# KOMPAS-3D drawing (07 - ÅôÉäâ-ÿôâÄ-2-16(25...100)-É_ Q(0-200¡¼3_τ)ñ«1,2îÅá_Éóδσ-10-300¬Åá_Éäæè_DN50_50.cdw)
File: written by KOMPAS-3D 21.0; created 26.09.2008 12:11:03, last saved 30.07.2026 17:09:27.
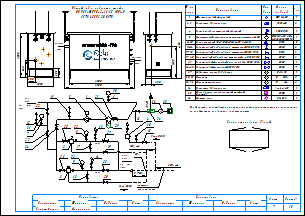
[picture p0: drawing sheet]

Sheets 1-2: A3, landscape

Document properties: Наименование: Макро:21; Автор: RaskoAdmin; Форматы листов документа: 2xA3; Полное имя файла: \\ur38nt01\Departments\КТО\КБ ПУРДГ\Заявки\Прайс-лист на типовые шкафы ГРПШ\ПУРДГ_стандарт_30_04_2026\ПУРДГ с РДСК\ПУРДГ-ШУГО-2-16(25...100)-Р_ Q(0-200нм3_ч)до1,2МПа_Рвых-10-300кПа_РДСК_DN50_50.cdw

Title block, sheet 1: Наименование: Пункт учета газа / ПУГ-Ш-400-Р / ЛГТИ.485922.001ТУ; designation: ЛГТИ.03.4411141; sheet number: 1; Количество листов документа: 2; organisation: ООО "ЭЛЬСТЕР Газэлектроника"; Форматы листов документа: A3; stored path: C:\Рабочие документы\Компас\ПУГ\Схема.cdw; Разработал: Устинов; Проверил: Кошкин; Утвердил: Кошкин
Title block, sheet 2: sheet number: 2; stored path: D:\Рабочие документы\Заявки\ПУРДГ\ПУРДГ-ШУЭО-2-100-Р 4411220.cdw; designation, second copy: ЛГТИ.03.4411141-

Views: Вид 1, Вид 2
Referenced files: wcvoit.frw
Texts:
  Normal
  № на
  схеме
  Усл.
  обозн.
  Марка
  (модель)
  Кол.
  Фильтр газовый фланцевый
  ФГ 16-50
  Регулятор давления газа
  РДСК-50
  Клапан предохранительный сбросной
  КПС DN20
  Измерительный комплекс с ротационным счетчиком Ду50
  СГ-ЭК-Р-(0,2...2,0)-
  Кран кнопочный VE-РАСКО-НЗ-1,6-G1/2-М20
  DN15
  Кран шаровой "под приварку" штуцерный DN20 PN16
  DN20
  Кран шаровой "под приварку" штуцерный DN15 PN16
  Кран шаровой "под приварку" штуцерный п/п DN20 PN16
  Кран шаровой фланцевый с мех. приводом DN50 PN16
  Кран шаровой фланцевый DN50 PN16
  DN50
  Индикатор перепада давления
  Манометр
  Манометр-напоромер
  Обогреватель газогорелочный шкафной
  (Эльтон")
  Счетчик газа
  Delta 15
  0...     МПа
  0...     кПа
  Venio-A-15
  ОГШН
  BK-G1,6
  Общий вид и габариты шкафа
  ПУРДГ-ШУГО-2-16(25...100)-Р
  Выход газа
  Вход газа
  logo-rasko-ge.png
  DN 1
  местное
  сопротивление
  Римп DN20
  Выход
  газа
  Р=     кПа
  Вход
  Р=       МПа
  PDI
  Схема открывания дверей
  Предприятие изготовитель может заменять комплектующие на аналогичные,
  не ухудшающие заявленных характеристик.
  Должность
  Конструктор
  Фамилия
  Подпись
  Дата
  Согласовано
  Максимкин
  Лист
  Листов
  POLYLINE_STYLE_0.18_RGB_0_0_0
  POLYLINE_STYLE_0.50_RGB_0_0_0
  POLYLINE_STYLE_0.34_RGB_0_0_0
  PHANTOM_RGB_0_0_0_SC_1_THICK_0.18
  K5LT_THIN_RGB_0_0_0_THICK_0.18
  K5LT32769_RGB_0_0_0_THICK_0.18
  K5LT12_RGB_0_0_0_SC_1_THICK_0.18
  K5LT_DASHED_RGB_0_0_0_SC_1_THICK_0.18
  ACISOTGL_RGB_0_0_0_SC_0.8_THICK_0.25
  CONTINUOUS_RGB_0_127_31_THICK_0.3
  CONTINUOUS_RGB_0_0_255_THICK_0.35
  CONTINUOUS_RGB_255_0_0_THICK_0.35
  POLYLINE_STYLE_0.25_RGB_0_0_0
  CONTINUOUS_RGB_0_0_0_THICK_0.5
  POLYLINE_STYLE_0.35_RGB_0_0_255
  CONTINUOUS_RGB_0_0_0_THICK_0.4
  CONTINUOUS_RGB_0_0_0_THICK_0.35
  НЕВИДИМАЯ_RGB_0_0_0_SC_0.3_THICK_0.25
  СONTINUOUS_RGB_0_0_0_THICK_0.25
  ОСЕВАЯ2_RGB_248_153_30_SC_0.3_THICK_0.25
  Без оформления
Dimensions and other numbers on the sheet: 1; 2, 3; 2; 4; 5; 6-10; 11-16; 6; 17, 18; 19, 20; 21; 22-28; 7; 29; 30, 31; 32, 33; 34; 35; 36; 1500; 250; 300; 1050; 550; 305; 2000; 4130; 2300; 5,,,7DN 1; 31; 12; 22; 23; 24; 11; 30; 25; 32; 8; 17; 13; 27; 19; 10; 15; 26; 33; 9; 3; 18; 14; 28; 20; 16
